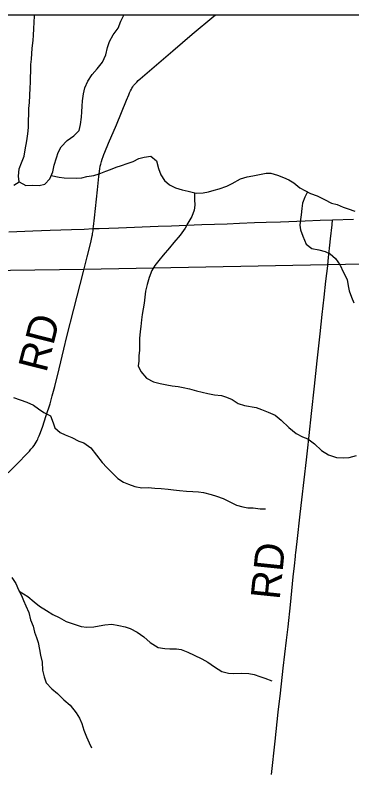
# Model space of a CAD drawing. Extents: x 0 to 1052, y -194 to 246.
# Drawn here: x 6.254 to 6.909, y 19.536 to 21.005 of the extents above; entities that cross this region are included whole.
import ezdxf

# ---------------------------------------------------------------- set-up
doc = ezdxf.new("R2010")
doc.units = 0
for name, color, linetype in [('GM_X_Corporation', 7, 'Continuous'), ('GM_X_County_Text', 7, 'Continuous'), ('GM_X_Major_River', 7, 'Continuous'), ('GM_X_Minor_River', 7, 'Continuous'), ('GM_X_Rail_Line', 7, 'Continuous'), ('GM_X_State_Route', 7, 'Continuous'), ('GM_X_Township_Road', 7, 'Continuous'), ('GM_X_Township_Road_Text', 7, 'Continuous')]:
    doc.layers.add(name, color=color, linetype=linetype)

msp = doc.modelspace()

# ---------------------------------------------------------------- linework, layer by layer
at = {"layer": 'GM_X_Corporation'}
msp.add_lwpolyline([(5.1788, 17.6981), (5.491, 17.9457), (6.1888, 18.4644), (6.5994, 18.7694), (6.8785, 18.9763), (8.1871, 19.9814), (8.6571, 20.341), (8.7822, 20.435), (8.7822, 21.0055), (1.9822, 21.0055), (1.9822, 14.2055)], dxfattribs=at)
msp.add_lwpolyline([(8.7822, 20.435), (8.7822, 21.0055), (5.5898, 21.0055), (5.6935, 20.5776), (5.9283, 19.6076), (5.992, 19.3448), (6.152, 18.6129), (6.1888, 18.4644), (6.5994, 18.7694), (6.8785, 18.9763), (8.1871, 19.9814), (8.6571, 20.341)], close=True, dxfattribs=at)
at = {"layer": 'GM_X_Major_River'}
msp.add_lwpolyline([(6.2514, 20.6749), (6.2621, 20.6812), (6.2749, 20.6739), (6.2878, 20.6748), (6.3007, 20.6743), (6.3117, 20.6764), (6.3217, 20.6869), (6.3272, 20.7009), (6.3301, 20.7134), (6.3344, 20.7277), (6.3376, 20.7383), (6.3438, 20.7496), (6.355, 20.7616), (6.3683, 20.7705), (6.3787, 20.7814), (6.3812, 20.7927), (6.3832, 20.8068), (6.3838, 20.8174), (6.3843, 20.8284), (6.3848, 20.839), (6.3873, 20.8522), (6.3897, 20.8643), (6.3952, 20.8768), (6.4041, 20.8899), (6.4137, 20.9008), (6.4237, 20.914), (6.4304, 20.9283), (6.434, 20.9423), (6.4375, 20.9544), (6.4445, 20.9672), (6.4546, 20.9803), (6.4597, 20.9939), (6.4647, 21.0041), (6.4653, 21.0055)], dxfattribs=at)
at = {"layer": 'GM_X_Minor_River'}
for points in [[(6.2621, 20.6812), (6.2605, 20.6924), (6.2621, 20.7068), (6.2664, 20.7185), (6.2714, 20.731), (6.2738, 20.7435), (6.277, 20.7609), (6.279, 20.7749), (6.2799, 20.7871), (6.2804, 20.8003), (6.2809, 20.8129), (6.281, 20.8239), (6.2819, 20.8356), (6.2828, 20.8493), (6.2833, 20.8641), (6.2837, 20.8747), (6.2838, 20.8853), (6.2843, 20.8952), (6.2848, 20.9096), (6.2857, 20.9199), (6.2874, 20.9411), (6.289, 20.9563), (6.2899, 20.9665), (6.2907, 20.9786), (6.2912, 20.9915), (6.2917, 21.0033), (6.2919, 21.0055)], [(6.3244, 20.6936), (6.3398, 20.6905), (6.3496, 20.6889), (6.3735, 20.6887), (6.3838, 20.689), (6.3933, 20.6915), (6.4073, 20.6937), (6.4176, 20.6966), (6.4302, 20.7018), (6.4397, 20.7055), (6.4507, 20.7096), (6.461, 20.7129), (6.4717, 20.7166), (6.4835, 20.7211), (6.4945, 20.7267), (6.5048, 20.7292), (6.5181, 20.7314), (6.529, 20.7218), (6.5327, 20.7074), (6.5375, 20.6948), (6.5446, 20.6837), (6.5544, 20.6757), (6.5657, 20.6695), (6.5786, 20.6656), (6.5907, 20.6628), (6.6058, 20.6592), (6.6195, 20.6599), (6.6298, 20.6617), (6.6412, 20.665), (6.6511, 20.6676), (6.6655, 20.6731), (6.6762, 20.6783), (6.6926, 20.6873), (6.7055, 20.691), (6.7162, 20.6932), (6.7295, 20.6953), (6.742, 20.6979), (6.7515, 20.6982), (6.7644, 20.6939), (6.7761, 20.69), (6.7863, 20.6849), (6.7961, 20.6792), (6.8074, 20.6699), (6.8176, 20.6645), (6.8286, 20.6587), (6.8411, 20.6541), (6.8558, 20.6471), (6.869, 20.6398), (6.88, 20.637), (6.8917, 20.632), (6.9019, 20.6285), (6.9148, 20.6242)], [(6.603, 20.6599), (6.6031, 20.6471), (6.6034, 20.6357), (6.6021, 20.6263), (6.5979, 20.6138), (6.5902, 20.6009), (6.5844, 20.5911), (6.5748, 20.5775), (6.5629, 20.5636), (6.5544, 20.5531), (6.5418, 20.5388), (6.5333, 20.5286), (6.5257, 20.5188), (6.5199, 20.5086), (6.5145, 20.495), (6.5105, 20.4817), (6.5078, 20.4685), (6.5061, 20.4567), (6.5049, 20.4453), (6.5029, 20.434), (6.5009, 20.4234), (6.4997, 20.4131), (6.4988, 20.4002), (6.4972, 20.3904), (6.4959, 20.3763), (6.4962, 20.365), (6.4957, 20.354), (6.4949, 20.343), (6.4944, 20.3327), (6.4936, 20.3232), (6.4984, 20.3126), (6.5097, 20.2996), (6.5229, 20.2926), (6.5362, 20.2894), (6.549, 20.2863), (6.5593, 20.2843), (6.571, 20.2831), (6.5805, 20.2814), (6.593, 20.2787), (6.6066, 20.2751), (6.6176, 20.272), (6.6289, 20.2696), (6.6418, 20.2672), (6.6551, 20.266), (6.6649, 20.2628), (6.6759, 20.2578), (6.688, 20.2505), (6.7001, 20.2462), (6.7228, 20.2422), (6.7334, 20.2387), (6.7462, 20.2336), (6.7599, 20.2278), (6.7715, 20.2175), (6.7862, 20.2037), (6.8005, 20.1918), (6.813, 20.1852), (6.8232, 20.1817), (6.8364, 20.1717), (6.8499, 20.1587), (6.8635, 20.1502), (6.879, 20.1455), (6.8927, 20.1446), (6.9037, 20.1453), (6.9178, 20.149)], [(6.8224, 20.662), (6.8175, 20.6513), (6.8128, 20.6395), (6.8116, 20.6297), (6.8104, 20.6172), (6.8088, 20.6077), (6.8079, 20.5971), (6.809, 20.5876), (6.8134, 20.5754), (6.8197, 20.5601), (6.831, 20.5513), (6.8443, 20.5493), (6.8568, 20.5461), (6.8666, 20.5415), (6.8768, 20.5319), (6.8858, 20.5189), (6.8921, 20.506), (6.8996, 20.4911), (6.9017, 20.4793), (6.9035, 20.4694), (6.908, 20.4569), (6.9124, 20.4458)], [(6.251, 20.2617), (6.2642, 20.2574), (6.2771, 20.2531), (6.2895, 20.2469), (6.2997, 20.2396), (6.3099, 20.2327), (6.3227, 20.2265), (6.3279, 20.2124), (6.3313, 20.2029), (6.3414, 20.194), (6.3516, 20.1894), (6.3645, 20.184), (6.3781, 20.177), (6.3879, 20.1735), (6.4011, 20.1643), (6.412, 20.1498), (6.4232, 20.1356), (6.4323, 20.1257), (6.4439, 20.1138), (6.4537, 20.1046), (6.465, 20.0973), (6.4748, 20.0934), (6.487, 20.0887), (6.5006, 20.0859), (6.5127, 20.0866), (6.526, 20.0857), (6.5378, 20.0852), (6.5514, 20.0836), (6.562, 20.082), (6.5738, 20.0811), (6.5874, 20.0798), (6.5999, 20.079), (6.6109, 20.0785), (6.6204, 20.0769), (6.6352, 20.0733), (6.6454, 20.0698), (6.6586, 20.0652), (6.6703, 20.0594), (6.6847, 20.0528), (6.6968, 20.0493), (6.7067, 20.0476), (6.7169, 20.0472), (6.7305, 20.0452), (6.7408, 20.0454)], [(6.2475, 19.9121), (6.2553, 19.8999), (6.2609, 19.8877), (6.2662, 19.877), (6.2702, 19.8671), (6.2751, 19.8565), (6.2807, 19.8439), (6.2839, 19.8298), (6.2891, 19.8169), (6.2917, 19.8054), (6.2954, 19.7952), (6.2987, 19.7853), (6.3013, 19.772), (6.3031, 19.7609), (6.3064, 19.7472), (6.307, 19.7317), (6.3107, 19.7184), (6.3144, 19.7069), (6.3253, 19.6955), (6.3366, 19.6862), (6.3486, 19.674), (6.361, 19.6636), (6.3727, 19.6487), (6.379, 19.6384), (6.3839, 19.6277), (6.3879, 19.6152), (6.3927, 19.6022), (6.3979, 19.59), (6.4028, 19.5805)], [(6.2621, 19.8853), (6.279, 19.875), (6.2911, 19.8647), (6.3013, 19.8562), (6.3152, 19.8474), (6.3277, 19.8397), (6.3398, 19.8342), (6.3534, 19.8265), (6.367, 19.8218), (6.3825, 19.8168), (6.3935, 19.8155), (6.4068, 19.8158), (6.4174, 19.818), (6.4288, 19.8198), (6.4421, 19.8208), (6.4557, 19.8188), (6.4678, 19.8156), (6.4777, 19.8129), (6.4913, 19.8055), (6.5041, 19.7963), (6.5165, 19.7852), (6.532, 19.7759), (6.5449, 19.7739), (6.5551, 19.7731), (6.5676, 19.7733), (6.5771, 19.7717), (6.5896, 19.7667), (6.6021, 19.7605), (6.6168, 19.7539), (6.6289, 19.7474), (6.6417, 19.7378), (6.656, 19.7289), (6.6689, 19.7257), (6.6795, 19.7253), (6.6943, 19.7255), (6.7084, 19.725), (6.719, 19.723), (6.7296, 19.7191), (6.7394, 19.716), (6.7534, 19.7109)]]:
    msp.add_lwpolyline(points, dxfattribs=at)
at = {"layer": 'GM_X_Rail_Line'}
msp.add_lwpolyline([(1.9822, 20.4716), (2.0551, 20.4708), (2.4106, 20.4737), (3.1102, 20.4767), (3.8818, 20.4767), (4.2729, 20.4769), (4.6986, 20.4854), (5.3445, 20.496), (5.674, 20.5018), (6.3876, 20.5117), (6.862, 20.5208), (7.7527, 20.5376), (8.5619, 20.5538), (8.7822, 20.5583)], dxfattribs=at)
at = {"layer": 'GM_X_State_Route'}
msp.add_lwpolyline([(6.2416, 20.584), (6.2887, 20.5859), (6.3223, 20.587), (6.3639, 20.5887), (6.3881, 20.5895), (6.406, 20.5902), (6.4173, 20.5907), (6.4551, 20.5918), (6.5321, 20.5951), (6.5582, 20.596), (6.6172, 20.5981), (6.642, 20.5991), (6.6662, 20.5999), (6.6904, 20.6006), (6.7196, 20.6019), (6.7419, 20.6027), (6.7699, 20.6037), (6.8183, 20.6053), (6.8469, 20.6066), (6.8713, 20.6075), (6.9121, 20.6089)], dxfattribs=at)
at = {"layer": 'GM_X_Township_Road'}
for points in [[(6.406, 20.5902), (6.4065, 20.5946), (6.4083, 20.6113), (6.414, 20.6657), (6.4167, 20.6916), (6.4186, 20.7064), (6.4196, 20.7114), (6.4205, 20.7155), (6.4218, 20.7206), (6.4231, 20.7251), (6.425, 20.7303), (6.4265, 20.7345), (6.4285, 20.7392), (6.4357, 20.7562), (6.451, 20.7922), (6.4708, 20.8398), (6.475, 20.8502), (6.4767, 20.8543), (6.4784, 20.8582), (6.4802, 20.8616), (6.4813, 20.8636), (6.483, 20.8662), (6.4844, 20.8683), (6.4872, 20.8716), (6.4906, 20.8752), (6.4936, 20.878), (6.4975, 20.8815), (6.5105, 20.8931), (6.5606, 20.9358), (6.5984, 20.9681), (6.6403, 21.0033), (6.6428, 21.0055)], [(6.7524, 19.5287), (6.7595, 19.5935), (6.7658, 19.6502), (6.77, 19.6872), (6.7755, 19.7353), (6.7787, 19.7625), (6.7818, 19.7902), (6.7847, 19.8162), (6.7895, 19.8588), (6.7948, 19.9132), (6.7971, 19.9347), (6.7991, 19.9525), (6.7994, 19.9557), (6.7999, 19.9595), (6.8023, 19.9816), (6.8084, 20.0353), (6.8116, 20.0631), (6.8204, 20.1408), (6.8223, 20.1581), (6.8258, 20.1877), (6.8302, 20.2309), (6.8361, 20.284), (6.8415, 20.3334), (6.8471, 20.3859), (6.851, 20.423), (6.8549, 20.4569), (6.8583, 20.4884), (6.8619, 20.518), (6.8628, 20.5279), (6.8675, 20.5704), (6.8703, 20.5976), (6.8713, 20.6075)], [(6.2406, 20.1156), (6.263, 20.138), (6.273, 20.1482), (6.2819, 20.1577), (6.2849, 20.1611), (6.2884, 20.1652), (6.2908, 20.1686), (6.2931, 20.1718), (6.295, 20.1752), (6.2967, 20.1783), (6.298, 20.181), (6.2991, 20.1833), (6.3007, 20.1871), (6.3022, 20.1908), (6.3071, 20.2042), (6.3146, 20.2266), (6.322, 20.2497), (6.3264, 20.2652), (6.3311, 20.2832), (6.3394, 20.3177), (6.3486, 20.3557), (6.3549, 20.3804), (6.368, 20.4335), (6.3868, 20.5069), (6.3944, 20.5357), (6.4012, 20.5634), (6.4019, 20.5664), (6.4026, 20.5697), (6.4033, 20.5731), (6.404, 20.5762), (6.4044, 20.5785), (6.4047, 20.5807), (6.4051, 20.5833), (6.4056, 20.586), (6.406, 20.5902)]]:
    msp.add_lwpolyline(points, dxfattribs=at)

# ---------------------------------------------------------------- texts
at = {"layer": 'GM_X_County_Text'}
msp.add_text('HIGHLAND COUNTY', height=0.189394, rotation=37.2438, dxfattribs=at).set_placement((6.5935, 18.2705))
at = {"layer": 'GM_X_Township_Road_Text'}
for rotation, p in [(75.7263, (6.3146, 20.3087)), (84.0908, (6.7683, 19.8674))]:
    msp.add_text('RD', height=0.05682, rotation=rotation, dxfattribs=at).set_placement(p)

doc.saveas('drawing.dxf')
